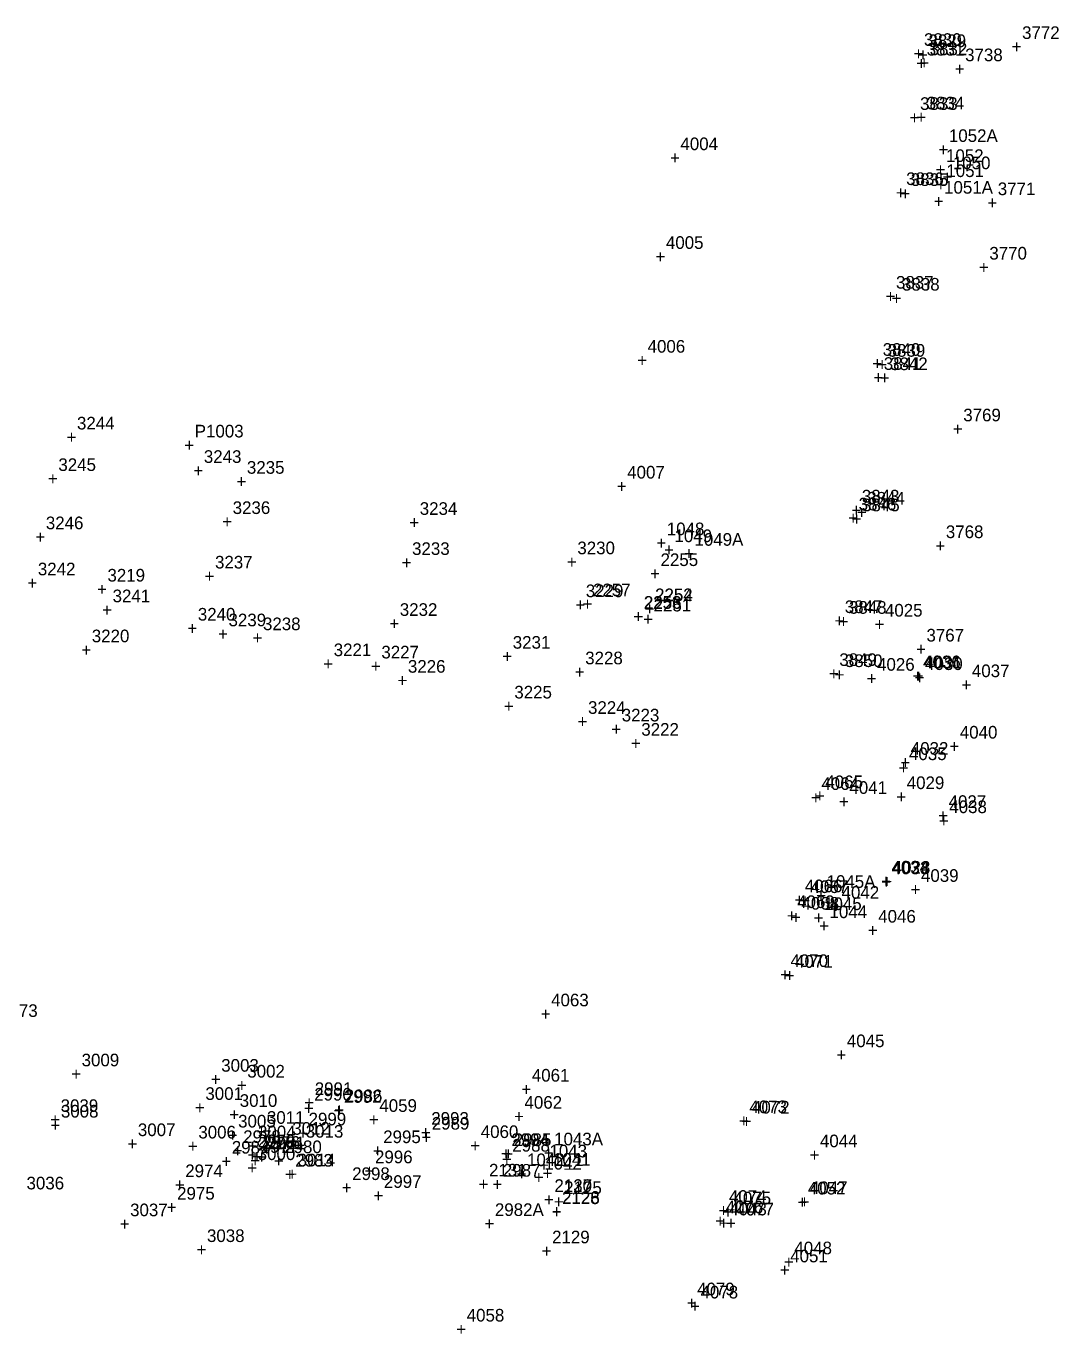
# Model space of a CAD drawing. Extents: x 1136220 to 1137808, y 528804 to 531215.
# Drawn here: x 1137233.5 to 1137437.8, y 529626.9 to 529885.6 of the extents above; entities that cross this region are included whole.
import ezdxf

# ---------------------------------------------------------------- set-up
doc = ezdxf.new("R2010")
doc.units = 0
for name, color, linetype in [('S_Buildings', 7, 'Continuous'), ('S_Buildings_SillElevation', 7, 'Continuous'), ('S_Drainage_CB', 7, 'Continuous'), ('S_Drainage_Culvert_Top', 7, 'Continuous'), ('S_Drainage_Invert', 7, 'Continuous'), ('S_Drainage_Sump', 7, 'Continuous'), ('S_Fencing_PostAndRail', 7, 'Continuous'), ('S_Ground_Elevation', 7, 'Continuous'), ('S_Ground_SpotElevation', 7, 'Continuous'), ('S_Property_ConcPad', 7, 'Continuous'), ('S_Property_IronPipeFound', 7, 'Continuous'), ('S_Roadway_Centerline', 7, 'Continuous'), ('S_Roadway_Edge_Pavement', 7, 'Continuous'), ('S_Utilities_Pole_Joint', 7, 'Continuous'), ('S_Utilities_UG_Gas_Line', 7, 'Continuous'), ('S_Utilities_UG_Sanitary_MH', 7, 'Continuous'), ('S_Utilities_UG_Water_Gate', 7, 'Continuous'), ('S_Utilities_UG_Water_Line', 7, 'Continuous'), ('S_Utilities_UG_Water_Shutoff', 7, 'Continuous')]:
    doc.layers.add(name, color=color, linetype=linetype)

msp = doc.modelspace()

# ---------------------------------------------------------------- texts
at = {"layer": 'S_Buildings'}
for s, p in [('2986', (1137296.49, 529672.76)), ('+', (1137294.43, 529670.01)), ('2985', (1137329.93, 529664.08)), ('2984', (1137274.15, 529662.58)), ('+', (1137327.87, 529661.33)), ('+', (1137272.09, 529659.83)), ('2983', (1137286.71, 529660.01)), ('+', (1137284.65, 529657.26)), ('2982A', (1137326.2, 529650.25)), ('+', (1137324.14, 529647.5))]:
    msp.add_text(s, height=2.5, dxfattribs=at).set_placement(p)
at = {"layer": 'S_Buildings_SillElevation'}
for s, p in [('3772', (1137430.49, 529883.06)), ('+', (1137428.43, 529880.31)), ('4004', (1137362.9, 529861.07)), ('+', (1137360.84, 529858.32)), ('3771', (1137425.68, 529852.17)), ('+', (1137423.62, 529849.42)), ('4005', (1137360.03, 529841.54)), ('3770', (1137424.01, 529839.43)), ('+', (1137357.97, 529838.79)), ('+', (1137421.95, 529836.68)), ('4006', (1137356.41, 529821.01)), ('+', (1137354.35, 529818.26)), ('3769', (1137418.85, 529807.43)), ('+', (1137416.79, 529804.68)), ('4007', (1137352.37, 529796.11)), ('+', (1137350.31, 529793.36)), ('3768', (1137415.41, 529784.33)), ('+', (1137413.34, 529781.58)), ('3767', (1137411.57, 529763.88)), ('+', (1137409.51, 529761.13)), ('4027', (1137415.95, 529730.96)), ('+', (1137413.89, 529728.21)), ('4046', (1137402.03, 529708.27)), ('+', (1137399.97, 529705.52)), ('4063', (1137337.32, 529691.72)), ('+', (1137335.26, 529688.97)), ('4045', (1137395.83, 529683.64)), ('+', (1137393.76, 529680.89)), ('4061', (1137333.5, 529676.83)), ('+', (1137331.44, 529674.08)), ('4059', (1137303.34, 529670.84)), ('4062', (1137332.05, 529671.47)), ('+', (1137329.99, 529668.72)), ('+', (1137301.28, 529668.09)), ('4060', (1137323.4, 529665.67)), ('4044', (1137390.5, 529663.84)), ('+', (1137321.33, 529662.92)), ('+', (1137388.44, 529661.09)), ('4058', (1137320.62, 529629.37)), ('+', (1137318.56, 529626.62))]:
    msp.add_text(s, height=2.5, dxfattribs=at).set_placement(p)
at = {"layer": 'S_Drainage_CB'}
for s, p in [('2976', (1137280.22, 529663.53)), ('+', (1137278.16, 529660.78))]:
    msp.add_text(s, height=2.5, dxfattribs=at).set_placement(p)
at = {"layer": 'S_Drainage_Culvert_Top'}
for s, p in [('1052A', (1137416.01, 529862.69)), ('+', (1137413.95, 529859.94)), ('1051A', (1137415.06, 529852.46)), ('+', (1137413, 529849.71)), ('1049A', (1137365.68, 529782.82)), ('+', (1137363.62, 529780.07)), ('2255', (1137358.97, 529778.81)), ('+', (1137356.9, 529776.06)), ('2257', (1137345.6, 529772.83)), ('2254', (1137357.9, 529771.85)), ('+', (1137343.54, 529770.08)), ('2256', (1137355.69, 529770.34)), ('+', (1137353.62, 529767.59)), ('+', (1137355.84, 529769.1)), ('1045A', (1137391.81, 529715.15)), ('+', (1137389.75, 529712.4)), ('2978', (1137276.4, 529664.69)), ('1043A', (1137337.92, 529664.22)), ('+', (1137274.34, 529661.94)), ('2980', (1137284.52, 529662.68)), ('+', (1137335.86, 529661.47)), ('+', (1137282.46, 529659.93)), ('2131', (1137325.03, 529658.06)), ('1042', (1137335.97, 529659.43)), ('+', (1137333.91, 529656.68)), ('+', (1137322.97, 529655.31)), ('2130', (1137337.97, 529655)), ('2128', (1137339.49, 529652.6)), ('+', (1137335.91, 529652.25)), ('+', (1137337.43, 529649.85)), ('2129', (1137337.51, 529644.84)), ('+', (1137335.45, 529642.09))]:
    msp.add_text(s, height=2.5, dxfattribs=at).set_placement(p)
at = {"layer": 'S_Drainage_Invert'}
for s, p in [('1052', (1137415.44, 529858.73)), ('+', (1137413.38, 529855.98)), ('1051', (1137415.51, 529855.75)), ('+', (1137413.45, 529853)), ('1049', (1137361.73, 529783.54)), ('+', (1137359.67, 529780.79)), ('2252', (1137357.87, 529771.86)), ('2253', (1137355.64, 529770.36)), ('+', (1137353.57, 529767.61)), ('+', (1137355.81, 529769.11)), ('1045', (1137391.32, 529710.76)), ('+', (1137389.26, 529708.01)), ('2979', (1137279.29, 529663.84)), ('2981', (1137281.16, 529663.44)), ('+', (1137277.23, 529661.09)), ('1043', (1137336.99, 529661.84)), ('+', (1137279.1, 529660.69)), ('+', (1137334.93, 529659.09)), ('2127', (1137337.98, 529655.01)), ('2126', (1137339.49, 529652.66)), ('+', (1137335.92, 529652.26)), ('+', (1137337.43, 529649.91))]:
    msp.add_text(s, height=2.5, dxfattribs=at).set_placement(p)
at = {"layer": 'S_Drainage_Sump'}
for s, p in [('1050', (1137416.8, 529857.3)), ('+', (1137414.74, 529854.55)), ('1048', (1137360.2, 529784.9)), ('+', (1137358.14, 529782.15)), ('1044', (1137392.4, 529709.17)), ('+', (1137390.34, 529706.42)), ('2977', (1137279.85, 529662.72)), ('+', (1137277.79, 529659.97)), ('1041', (1137337.7, 529660.2)), ('+', (1137335.64, 529657.45))]:
    msp.add_text(s, height=2.5, dxfattribs=at).set_placement(p)
at = {"layer": 'S_Fencing_PostAndRail'}
for s, p in [('4030', (1137411.3, 529758.24)), ('+', (1137409.24, 529755.49)), ('4029', (1137407.67, 529734.69)), ('+', (1137405.61, 529731.94)), ('4028', (1137404.9, 529717.95)), ('+', (1137402.83, 529715.2)), ('4047', (1137388.52, 529654.58)), ('+', (1137386.46, 529651.83)), ('4048', (1137385.44, 529642.67)), ('+', (1137383.37, 529639.92))]:
    msp.add_text(s, height=2.5, dxfattribs=at).set_placement(p)
at = {"layer": 'S_Ground_Elevation'}
for s, p in [('3244', (1137243.52, 529805.82)), ('+', (1137241.46, 529803.07)), ('3245', (1137239.84, 529797.61)), ('+', (1137237.78, 529794.86)), ('3236', (1137274.32, 529789.1)), ('+', (1137272.26, 529786.35)), ('3233', (1137309.81, 529781)), ('3242', (1137235.78, 529776.97)), ('+', (1137307.75, 529778.25)), ('+', (1137233.72, 529774.22)), ('3241', (1137250.57, 529771.65)), ('3229', (1137344.18, 529772.65)), ('+', (1137342.12, 529769.9)), ('+', (1137248.5, 529768.9)), ('3240', (1137267.43, 529768.02)), ('+', (1137265.37, 529765.27)), ('3226', (1137308.99, 529757.71)), ('4036', (1137410.9, 529758.59)), ('4031', (1137411.1, 529758.57)), ('+', (1137306.93, 529754.96)), ('+', (1137408.84, 529755.84)), ('+', (1137409.04, 529755.82)), ('3225', (1137330.04, 529752.61)), ('+', (1137327.97, 529749.86)), ('3224', (1137344.62, 529749.57)), ('+', (1137342.56, 529746.82)), ('3223', (1137351.29, 529748.07)), ('+', (1137349.23, 529745.32)), ('3222', (1137355.16, 529745.25)), ('+', (1137353.1, 529742.5)), ('4032', (1137408.47, 529741.48)), ('+', (1137406.41, 529738.73)), ('4035', (1137408.12, 529740.42)), ('+', (1137406.06, 529737.67)), ('4034', (1137404.66, 529717.99)), ('4033', (1137404.7, 529717.84)), ('+', (1137402.59, 529715.24)), ('+', (1137402.64, 529715.09)), ('1042_1', (1137332.56, 529660.11)), ('+', (1137330.5, 529657.36)), ('4052', (1137388.1, 529654.5)), ('+', (1137386.04, 529651.75)), ('4051', (1137384.62, 529641.08)), ('+', (1137382.56, 529638.33))]:
    msp.add_text(s, height=2.5, dxfattribs=at).set_placement(p)
at = {"layer": 'S_Ground_SpotElevation'}
for s, p in [('4037', (1137420.56, 529756.83)), ('+', (1137418.5, 529754.08)), ('4040', (1137418.17, 529744.68)), ('+', (1137416.11, 529741.93)), ('4038', (1137416.09, 529729.94)), ('+', (1137414.03, 529727.19)), ('4039', (1137410.49, 529716.34)), ('+', (1137408.43, 529713.59)), ('3003', (1137272.06, 529678.79)), ('3002', (1137277.21, 529677.63)), ('+', (1137270, 529676.04)), ('+', (1137275.15, 529674.88)), ('3039', (1137240.29, 529670.82)), ('3001', (1137268.92, 529673.21)), ('3008', (1137240.34, 529669.72)), ('+', (1137266.86, 529670.46)), ('2999', (1137289.34, 529668.17)), ('+', (1137238.23, 529668.07)), ('+', (1137238.27, 529666.97)), ('3007', (1137255.57, 529666.05)), ('3006', (1137267.53, 529665.58)), ('3005', (1137275.4, 529667.75)), ('3004', (1137279.33, 529665.62)), ('+', (1137273.34, 529665)), ('+', (1137287.28, 529665.42)), ('2995', (1137304.1, 529664.66)), ('+', (1137253.51, 529663.3)), ('+', (1137265.47, 529662.83)), ('+', (1137277.27, 529662.87)), ('3000', (1137279.27, 529661.31)), ('+', (1137302.04, 529661.91)), ('2996', (1137302.48, 529660.68)), ('+', (1137277.21, 529658.56)), ('2987', (1137327.77, 529658.03)), ('3036', (1137233.54, 529655.51)), ('2998', (1137297.97, 529657.36)), ('+', (1137300.42, 529657.93)), ('2997', (1137304.24, 529655.8)), ('+', (1137295.91, 529654.62)), ('+', (1137302.18, 529653.05)), ('+', (1137325.71, 529655.28)), ('3037', (1137254.03, 529650.2)), ('+', (1137251.97, 529647.45)), ('3038', (1137269.24, 529645.1)), ('+', (1137267.18, 529642.35))]:
    msp.add_text(s, height=2.5, dxfattribs=at).set_placement(p)
at = {"layer": 'S_Property_ConcPad'}
for s, p in [('2991', (1137290.56, 529674.18)), ('+', (1137288.49, 529671.43)), ('2990', (1137290.46, 529673.07)), ('2992', (1137296.34, 529672.64)), ('+', (1137288.4, 529670.32)), ('+', (1137294.28, 529669.89)), ('2993', (1137313.61, 529668.3)), ('2989', (1137313.72, 529667.33)), ('+', (1137311.54, 529665.55)), ('+', (1137311.66, 529664.58)), ('2994', (1137329.46, 529664.09)), ('2988', (1137329.64, 529662.98)), ('+', (1137327.4, 529661.34)), ('+', (1137327.58, 529660.23))]:
    msp.add_text(s, height=2.5, dxfattribs=at).set_placement(p)
at = {"layer": 'S_Property_IronPipeFound'}
for s, p in [('P1003', (1137266.82, 529804.24)), ('+', (1137264.76, 529801.49))]:
    msp.add_text(s, height=2.5, dxfattribs=at).set_placement(p)
at = {"layer": 'S_Roadway_Centerline'}
for s, p in [('3246', (1137237.36, 529786.09)), ('+', (1137235.3, 529783.34)), ('3237', (1137270.83, 529778.32)), ('+', (1137268.77, 529775.57)), ('3232', (1137307.38, 529768.95)), ('+', (1137305.32, 529766.2)), ('3231', (1137329.73, 529762.46)), ('+', (1137327.67, 529759.71)), ('3228', (1137344.06, 529759.37)), ('+', (1137342, 529756.62))]:
    msp.add_text(s, height=2.5, dxfattribs=at).set_placement(p)
at = {"layer": 'S_Roadway_Edge_Pavement'}
for s, p in [('3243', (1137268.62, 529799.21)), ('+', (1137266.56, 529796.46)), ('3235', (1137277.14, 529797.06)), ('+', (1137275.08, 529794.31)), ('3234', (1137311.33, 529788.93)), ('+', (1137309.27, 529786.18)), ('3230', (1137342.51, 529781.14)), ('+', (1137340.45, 529778.39)), ('3239', (1137273.5, 529766.89)), ('3238', (1137280.32, 529766.12)), ('+', (1137271.44, 529764.14)), ('+', (1137278.26, 529763.37)), ('3227', (1137303.74, 529760.53)), ('+', (1137301.68, 529757.78)), ('3009', (1137244.44, 529679.85)), ('+', (1137242.38, 529677.1)), ('3010', (1137275.72, 529671.83)), ('+', (1137273.66, 529669.08)), ('3011', (1137281.1, 529668.48)), ('3012', (1137286.12, 529666.32)), ('3013', (1137288.78, 529665.74)), ('+', (1137279.04, 529665.73)), ('+', (1137284.06, 529663.57)), ('+', (1137286.72, 529662.99)), ('3014', (1137287.18, 529660.06)), ('+', (1137285.11, 529657.31))]:
    msp.add_text(s, height=2.5, dxfattribs=at).set_placement(p)
at = {"layer": 'S_Utilities_Pole_Joint'}
for s, p in [('3221', (1137294.31, 529760.98)), ('+', (1137292.25, 529758.23))]:
    msp.add_text(s, height=2.5, dxfattribs=at).set_placement(p)
at = {"layer": 'S_Utilities_UG_Gas_Line'}
for s, p in [('3219', (1137249.55, 529775.74)), ('+', (1137247.49, 529772.99)), ('3220', (1137246.45, 529763.73)), ('+', (1137244.39, 529760.98)), ('2973', (1137228.31, 529689.62))]:
    msp.add_text(s, height=2.5, dxfattribs=at).set_placement(p)
at = {"layer": 'S_Utilities_UG_Sanitary_MH'}
for s, p in [('2251', (1137357.59, 529769.83)), ('+', (1137355.53, 529767.08)), ('2974', (1137264.94, 529657.93)), ('+', (1137262.88, 529655.18)), ('2975', (1137263.33, 529653.48)), ('2125', (1137339.91, 529654.59)), ('+', (1137261.27, 529650.73)), ('+', (1137337.85, 529651.84))]:
    msp.add_text(s, height=2.5, dxfattribs=at).set_placement(p)
at = {"layer": 'S_Utilities_UG_Water_Gate'}
for s, p in [('3738', (1137419.22, 529878.66)), ('+', (1137417.16, 529875.91)), ('4041', (1137396.33, 529733.74)), ('+', (1137394.27, 529730.99)), ('4042', (1137394.78, 529713)), ('+', (1137392.72, 529710.25)), ('4043', (1137372.56, 529650.37)), ('+', (1137370.5, 529647.62))]:
    msp.add_text(s, height=2.5, dxfattribs=at).set_placement(p)
at = {"layer": 'S_Utilities_UG_Water_Line'}
for s, p in [('3830', (1137411.08, 529881.69)), ('3829', (1137411.97, 529881.45)), ('+', (1137409.02, 529878.94)), ('+', (1137409.91, 529878.7)), ('3831', (1137411.63, 529879.78)), ('3832', (1137412.21, 529879.85)), ('+', (1137409.57, 529877.03)), ('+', (1137410.15, 529877.1)), ('3833', (1137410.3, 529869.03)), ('3834', (1137411.61, 529869.13)), ('+', (1137408.24, 529866.28)), ('+', (1137409.55, 529866.38)), ('3836', (1137407.56, 529854.17)), ('3835', (1137408.48, 529853.99)), ('+', (1137405.5, 529851.42)), ('+', (1137406.42, 529851.24)), ('3837', (1137405.55, 529833.67)), ('3838', (1137406.74, 529833.29)), ('+', (1137403.49, 529830.92)), ('+', (1137404.68, 529830.54)), ('3840', (1137402.92, 529820.39)), ('3839', (1137403.89, 529820.21)), ('+', (1137400.86, 529817.64)), ('+', (1137401.83, 529817.46)), ('3841', (1137403.13, 529817.61)), ('3842', (1137404.38, 529817.56)), ('+', (1137401.07, 529814.86)), ('+', (1137402.32, 529814.81)), ('3846', (1137398.16, 529789.82)), ('3843', (1137398.79, 529791.38)), ('3844', (1137399.86, 529790.96)), ('+', (1137396.73, 529788.63)), ('+', (1137397.8, 529788.21)), ('3845', (1137398.83, 529789.64)), ('+', (1137396.1, 529787.07)), ('+', (1137396.77, 529786.89)), ('3847', (1137395.42, 529769.51)), ('3848', (1137396.24, 529769.37)), ('+', (1137393.36, 529766.76)), ('+', (1137394.18, 529766.62)), ('3849', (1137394.33, 529759.04)), ('3850', (1137395.44, 529758.83)), ('+', (1137392.27, 529756.29)), ('+', (1137393.38, 529756.08)), ('4064', (1137390.78, 529734.52)), ('4065', (1137391.57, 529734.88)), ('+', (1137388.72, 529731.77)), ('+', (1137389.51, 529732.13)), ('4066', (1137387.51, 529714.28)), ('4067', (1137388.65, 529714.13)), ('+', (1137385.45, 529711.53)), ('4069', (1137385.99, 529711.16)), ('+', (1137386.59, 529711.38)), ('4068', (1137386.84, 529710.84)), ('+', (1137383.93, 529708.41)), ('+', (1137384.78, 529708.09)), ('4070', (1137384.67, 529699.5)), ('4071', (1137385.58, 529699.34)), ('+', (1137382.61, 529696.75)), ('+', (1137383.52, 529696.59)), ('4073', (1137376.54, 529670.59)), ('4072', (1137377.06, 529670.51)), ('+', (1137374.48, 529667.84)), ('+', (1137375, 529667.76)), ('4074', (1137372.5, 529652.85)), ('4076', (1137371.85, 529650.77)), ('4075', (1137373.4, 529652.55)), ('4077', (1137373.97, 529650.35)), ('+', (1137369.79, 529648.02)), ('+', (1137370.44, 529650.1)), ('+', (1137371.34, 529649.8)), ('+', (1137371.91, 529647.6)), ('4079', (1137366.2, 529634.56)), ('4078', (1137366.88, 529633.94)), ('+', (1137364.14, 529631.81)), ('+', (1137364.82, 529631.19))]:
    msp.add_text(s, height=2.5, dxfattribs=at).set_placement(p)
at = {"layer": 'S_Utilities_UG_Water_Shutoff'}
for s, p in [('4025', (1137403.36, 529768.81)), ('+', (1137401.3, 529766.06)), ('4026', (1137401.8, 529758.1)), ('+', (1137399.74, 529755.35))]:
    msp.add_text(s, height=2.5, dxfattribs=at).set_placement(p)

doc.saveas('drawing.dxf')
